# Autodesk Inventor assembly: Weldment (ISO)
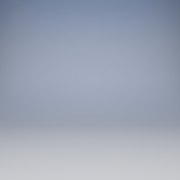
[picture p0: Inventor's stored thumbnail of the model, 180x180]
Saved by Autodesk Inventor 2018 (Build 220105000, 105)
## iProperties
Created: 2017-02
Part Number: Weldment (ISO)
Material: Ogólny
Document SubType Name: Weldment
Weld Material: Welded Aluminum-6061
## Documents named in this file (1)
- C:\Users\Joffi\Desktop\Templates.Base\Metric.Base\Weldment (ISO).iam
